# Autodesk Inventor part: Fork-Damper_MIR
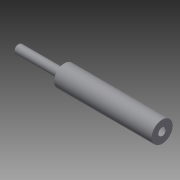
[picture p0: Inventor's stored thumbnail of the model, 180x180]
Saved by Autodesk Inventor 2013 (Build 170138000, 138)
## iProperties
Created: 2001-11
Part Number: Fork-Damper_MIR
Document SubType Name: Modeling
Designer: Autodesk, Inc.
Mass: 13.3721 g
Surface Area: 211.026 cm^2
Volume: 13.3721 cm^3
Density: 1 g/cm^3
Material: Generic
Author: Autodesk, Inc.
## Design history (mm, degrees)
derived "Fork-Damper.ipt"
body "Solid1"
tag "TaggingFeature2"
feature "DerivedBody::Fork-Damper.ipt" dims "d0" = 10
